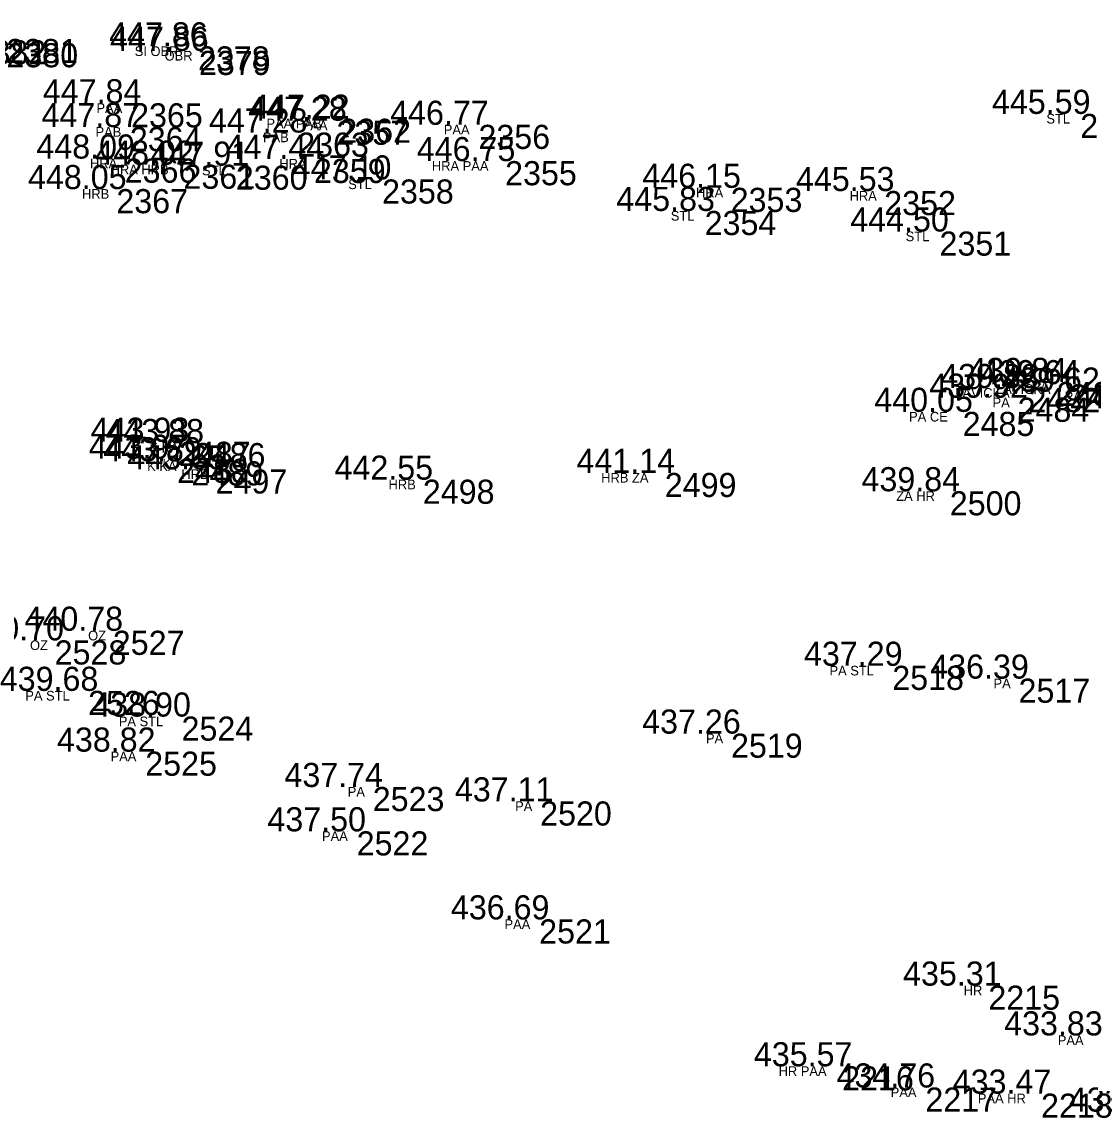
# Model space of a CAD drawing. Extents: x -639390 to -639075, y -1138747 to -1138358.
# Drawn here: x -639358.62 to -639325.37, y -1138592.34 to -1138558.24 of the extents above; entities that cross this region are included whole.
import ezdxf

# ---------------------------------------------------------------- set-up
doc = ezdxf.new("R2010")
doc.units = 0
for name, color, linetype in [('Vrstva 11', 7, 'Continuous'), ('Vrstva 12', 7, 'Continuous'), ('Vrstva 13', 7, 'Continuous'), ('Vrstva 57', 7, 'Continuous')]:
    doc.layers.add(name, color=color, linetype=linetype)

msp = doc.modelspace()

# ---------------------------------------------------------------- linework, layer by layer
at = {"layer": 'Vrstva 11'}
for p, q in [((-639353.42, -1138559), (-639353.42, -1138559)), ((-639353.39, -1138559.14), (-639353.39, -1138559.14)), ((-639355.5, -1138560.77), (-639355.5, -1138560.77)), ((-639349.11, -1138561.31), (-639349.11, -1138561.31)), ((-639349.02, -1138561.25), (-639349.02, -1138561.25)), ((-639325.96, -1138561.1), (-639325.96, -1138561.1)), ((-639355.54, -1138561.51), (-639355.54, -1138561.51)), ((-639350.33, -1138561.68), (-639350.33, -1138561.68)), ((-639344.69, -1138561.44), (-639344.69, -1138561.44)), ((-639355.7, -1138562.49), (-639355.7, -1138562.49)), ((-639353.87, -1138562.68), (-639353.87, -1138562.68)), ((-639352.24, -1138562.71), (-639352.24, -1138562.71)), ((-639349.81, -1138562.5), (-639349.81, -1138562.5)), ((-639343.86, -1138562.57), (-639343.86, -1138562.57)), ((-639347.69, -1138563.14), (-639347.69, -1138563.14)), ((-639355.96, -1138563.44), (-639355.96, -1138563.44)), ((-639336.84, -1138563.4), (-639336.84, -1138563.4)), ((-639332.06, -1138563.5), (-639332.06, -1138563.5)), ((-639337.65, -1138564.12), (-639337.65, -1138564.12)), ((-639330.34, -1138564.76), (-639330.34, -1138564.76)), ((-639326.69, -1138569.44), (-639326.69, -1138569.44)), ((-639326.3, -1138569.51), (-639326.3, -1138569.51)), ((-639327.57, -1138569.63), (-639327.57, -1138569.63)), ((-639325.67, -1138569.74), (-639325.67, -1138569.74)), ((-639327.91, -1138569.93), (-639327.91, -1138569.93)), ((-639329.62, -1138570.37), (-639329.62, -1138570.37)), ((-639354.01, -1138571.3), (-639354.01, -1138571.3)), ((-639353.55, -1138571.34), (-639353.55, -1138571.34)), ((-639354.07, -1138571.83), (-639354.07, -1138571.83)), ((-639353.62, -1138571.91), (-639353.62, -1138571.91)), ((-639352.87, -1138572.16), (-639352.87, -1138572.16)), ((-639346.42, -1138572.48), (-639346.42, -1138572.48)), ((-639338.89, -1138572.27), (-639338.89, -1138572.27)), ((-639330.02, -1138572.84), (-639330.02, -1138572.84)), ((-639356.07, -1138577.18), (-639356.07, -1138577.18)), ((-639357.88, -1138577.48), (-639357.88, -1138577.48)), ((-639331.81, -1138578.27), (-639331.81, -1138578.27)), ((-639327.88, -1138578.67), (-639327.88, -1138578.67)), ((-639356.84, -1138579.05), (-639356.84, -1138579.05)), ((-639353.93, -1138579.85), (-639353.93, -1138579.85)), ((-639336.83, -1138580.38), (-639336.83, -1138580.38)), ((-639355.06, -1138580.94), (-639355.06, -1138580.94)), ((-639347.98, -1138582.04), (-639347.98, -1138582.04)), ((-639342.77, -1138582.49), (-639342.77, -1138582.49)), ((-639348.48, -1138583.42), (-639348.48, -1138583.42)), ((-639342.8, -1138586.16), (-639342.8, -1138586.16)), ((-639328.82, -1138588.22), (-639328.82, -1138588.22)), ((-639325.58, -1138589.77), (-639325.58, -1138589.77)), ((-639333.37, -1138590.73), (-639333.37, -1138590.73)), ((-639330.78, -1138591.39), (-639330.78, -1138591.39)), ((-639327.18, -1138591.58), (-639327.18, -1138591.58))]:
    msp.add_line(p, q, dxfattribs=at)

# ---------------------------------------------------------------- texts
at = {"layer": 'Vrstva 12'}
for s, p in [('447.86 ', (-639355.906, -1138559)), ('447.86 ', (-639355.876, -1138559.14)), ('447.84 ', (-639357.969, -1138560.77)), ('447.28 ', (-639351.579, -1138561.31)), ('447.22 ', (-639351.489, -1138561.25)), ('445.59 ', (-639328.429, -1138561.1)), ('447.87 ', (-639358.009, -1138561.51)), ('447.28 ', (-639352.799, -1138561.68)), ('446.77 ', (-639347.159, -1138561.44)), ('448.09 ', (-639358.169, -1138562.49)), ('448.02 ', (-639356.339, -1138562.68)), ('447.91 ', (-639354.615, -1138562.71)), ('447.44 ', (-639352.279, -1138562.5)), ('446.75 ', (-639346.33, -1138562.57)), ('448.05 ', (-639358.43, -1138563.44)), ('447.10 ', (-639350.189, -1138563.14)), ('446.15 ', (-639339.31, -1138563.4)), ('445.53 ', (-639334.529, -1138563.5)), ('445.83 ', (-639340.119, -1138564.12)), ('444.50 ', (-639332.839, -1138564.76)), ('439.84 ', (-639329.159, -1138569.44)), ('439.64 ', (-639328.769, -1138569.51)), ('439.92 ', (-639330.379, -1138569.93)), ('439.88 ', (-639330.039, -1138569.63)), ('439.62 ', (-639328.139, -1138569.74)), ('440.05 ', (-639332.09, -1138570.37)), ('443.93 ', (-639356.479, -1138571.3)), ('443.88 ', (-639356.019, -1138571.34)), ('443.97 ', (-639356.539, -1138571.83)), ('443.89 ', (-639356.089, -1138571.91)), ('443.65 ', (-639355.34, -1138572.16)), ('441.14 ', (-639341.359, -1138572.27)), ('442.55 ', (-639348.89, -1138572.48)), ('439.84 ', (-639332.489, -1138572.84)), ('440.78 ', (-639358.539, -1138577.18)), ('440.70 ', (-639360.379, -1138577.48)), ('437.29 ', (-639334.279, -1138578.27)), ('436.39 ', (-639330.349, -1138578.67)), ('439.68 ', (-639359.309, -1138579.05)), ('438.90 ', (-639356.429, -1138579.85)), ('437.26 ', (-639339.316, -1138580.38)), ('438.82 ', (-639357.529, -1138580.94)), ('437.74 ', (-639350.449, -1138582.04)), ('437.11 ', (-639345.145, -1138582.49)), ('437.50 ', (-639350.979, -1138583.42)), ('436.69 ', (-639345.269, -1138586.16)), ('435.31 ', (-639331.195, -1138588.22)), ('433.83 ', (-639328.049, -1138589.77)), ('435.57 ', (-639335.839, -1138590.73)), ('434.76 ', (-639333.266, -1138591.39)), ('433.47 ', (-639329.649, -1138591.58)), ('433.26 ', (-639326.036, -1138592.14))]:
    msp.add_text(s, height=0.75, dxfattribs=at).set_placement(p)
at = {"layer": 'Vrstva 13'}
for s, p in [(' 2382', (-639360.37, -1138559.56)), (' 2381', (-639359.39, -1138559.52)), (' 2380', (-639359.38, -1138559.65)), (' 2378', (-639353.42, -1138559.75)), (' 2379', (-639353.39, -1138559.89)), (' 2365', (-639355.5, -1138561.52)), (' 2357', (-639349.11, -1138562.06)), (' 2362', (-639349.02, -1138562)), (' 2350', (-639325.96, -1138561.85)), (' 2364', (-639355.54, -1138562.26)), (' 2363', (-639350.33, -1138562.43)), (' 2356', (-639344.69, -1138562.19)), (' 2366', (-639355.7, -1138563.24)), (' 2361', (-639353.87, -1138563.43)), (' 2360', (-639352.24, -1138563.46)), (' 2359', (-639349.81, -1138563.25)), (' 2355', (-639343.86, -1138563.32)), (' 2358', (-639347.69, -1138563.89)), (' 2353', (-639336.84, -1138564.15)), (' 2367', (-639355.96, -1138564.19)), (' 2352', (-639332.06, -1138564.25)), (' 2354', (-639337.65, -1138564.87)), (' 2351', (-639330.34, -1138565.51)), (' 2483', (-639326.69, -1138570.19)), (' 2481', (-639326.3, -1138570.26)), (' 2482', (-639327.57, -1138570.38)), (' 2484', (-639327.91, -1138570.68)), (' 2485', (-639329.62, -1138571.12)), (' 2487', (-639354.01, -1138572.05)), (' 2486', (-639353.55, -1138572.09)), (' 2488', (-639354.07, -1138572.58)), (' 2489', (-639353.62, -1138572.66)), (' 2497', (-639352.87, -1138572.91)), (' 2499', (-639338.89, -1138573.02)), (' 2498', (-639346.42, -1138573.23)), (' 2500', (-639330.02, -1138573.59)), (' 2527', (-639356.07, -1138577.93)), (' 2528', (-639357.88, -1138578.23)), (' 2518', (-639331.81, -1138579.02)), (' 2517', (-639327.88, -1138579.42)), (' 2526', (-639356.84, -1138579.8)), (' 2524', (-639353.93, -1138580.6)), (' 2519', (-639336.83, -1138581.13)), (' 2525', (-639355.06, -1138581.69)), (' 2523', (-639347.98, -1138582.79)), (' 2520', (-639342.77, -1138583.24)), (' 2522', (-639348.48, -1138584.17)), (' 2521', (-639342.8, -1138586.91)), (' 2215', (-639328.82, -1138588.97)), (' 2216', (-639333.37, -1138591.48)), (' 2217', (-639330.78, -1138592.14)), (' 2218', (-639327.18, -1138592.33))]:
    msp.add_text(s, height=0.75, dxfattribs=at).set_placement(p)
at = {"layer": 'Vrstva 57'}
for s, p in [('SI OBR', (-639355.109, -1138559.3)), ('OBR', (-639354.179, -1138559.44)), ('PAA', (-639356.3, -1138561.07)), ('PAA PAB', (-639351.009, -1138561.55)), ('PAA', (-639349.91, -1138561.61)), ('STL', (-639326.735, -1138561.4)), ('PAB', (-639356.329, -1138561.81)), ('PAB', (-639351.119, -1138561.98)), ('PAA', (-639345.49, -1138561.74)), ('HRA', (-639356.5, -1138562.79)), ('HRA HRB', (-639355.859, -1138562.98)), ('STL', (-639353.015, -1138563.01)), ('HRA', (-639350.61, -1138562.8)), ('HRA PAA', (-639345.86, -1138562.87)), ('STL', (-639348.465, -1138563.44)), ('HRB', (-639356.749, -1138563.74)), ('HRA', (-639337.64, -1138563.7)), ('HRA', (-639332.86, -1138563.8)), ('STL', (-639338.425, -1138564.42)), ('STL', (-639331.115, -1138565.06)), ('LAVICKA', (-639328.3, -1138569.81)), ('PA', (-639327.19, -1138569.74)), ('LAVICKA', (-639329.57, -1138569.93)), ('PA', (-639326.17, -1138570.04)), ('PA', (-639328.41, -1138570.23)), ('PA CE', (-639331.008, -1138570.67)), ('K KA', (-639354.65, -1138571.64)), ('K', (-639354.185, -1138571.6)), ('K KA', (-639354.72, -1138572.21)), ('K', (-639354.245, -1138572.13)), ('HRB', (-639353.659, -1138572.46)), ('HRB', (-639347.209, -1138572.78)), ('HRB ZA', (-639340.59, -1138572.57)), ('ZA HR', (-639331.409, -1138573.14)), ('OZ', (-639356.559, -1138577.48)), ('OZ', (-639358.369, -1138577.78)), ('PA STL', (-639333.485, -1138578.57)), ('PA', (-639328.38, -1138578.97)), ('PA STL', (-639358.515, -1138579.35)), ('PA STL', (-639355.605, -1138580.15)), ('PA', (-639337.33, -1138580.68)), ('PAA', (-639355.86, -1138581.24)), ('PA', (-639348.48, -1138582.34)), ('PA', (-639343.27, -1138582.79)), ('PAA', (-639349.28, -1138583.72)), ('PAA', (-639343.6, -1138586.46)), ('HR', (-639329.309, -1138588.52)), ('PAA', (-639326.38, -1138590.07)), ('HR PAA', (-639335.07, -1138591.03)), ('PAA', (-639331.58, -1138591.69)), ('PAA HR', (-639328.869, -1138591.88))]:
    msp.add_text(s, height=0.3, dxfattribs=at).set_placement(p)

doc.saveas('drawing.dxf')
